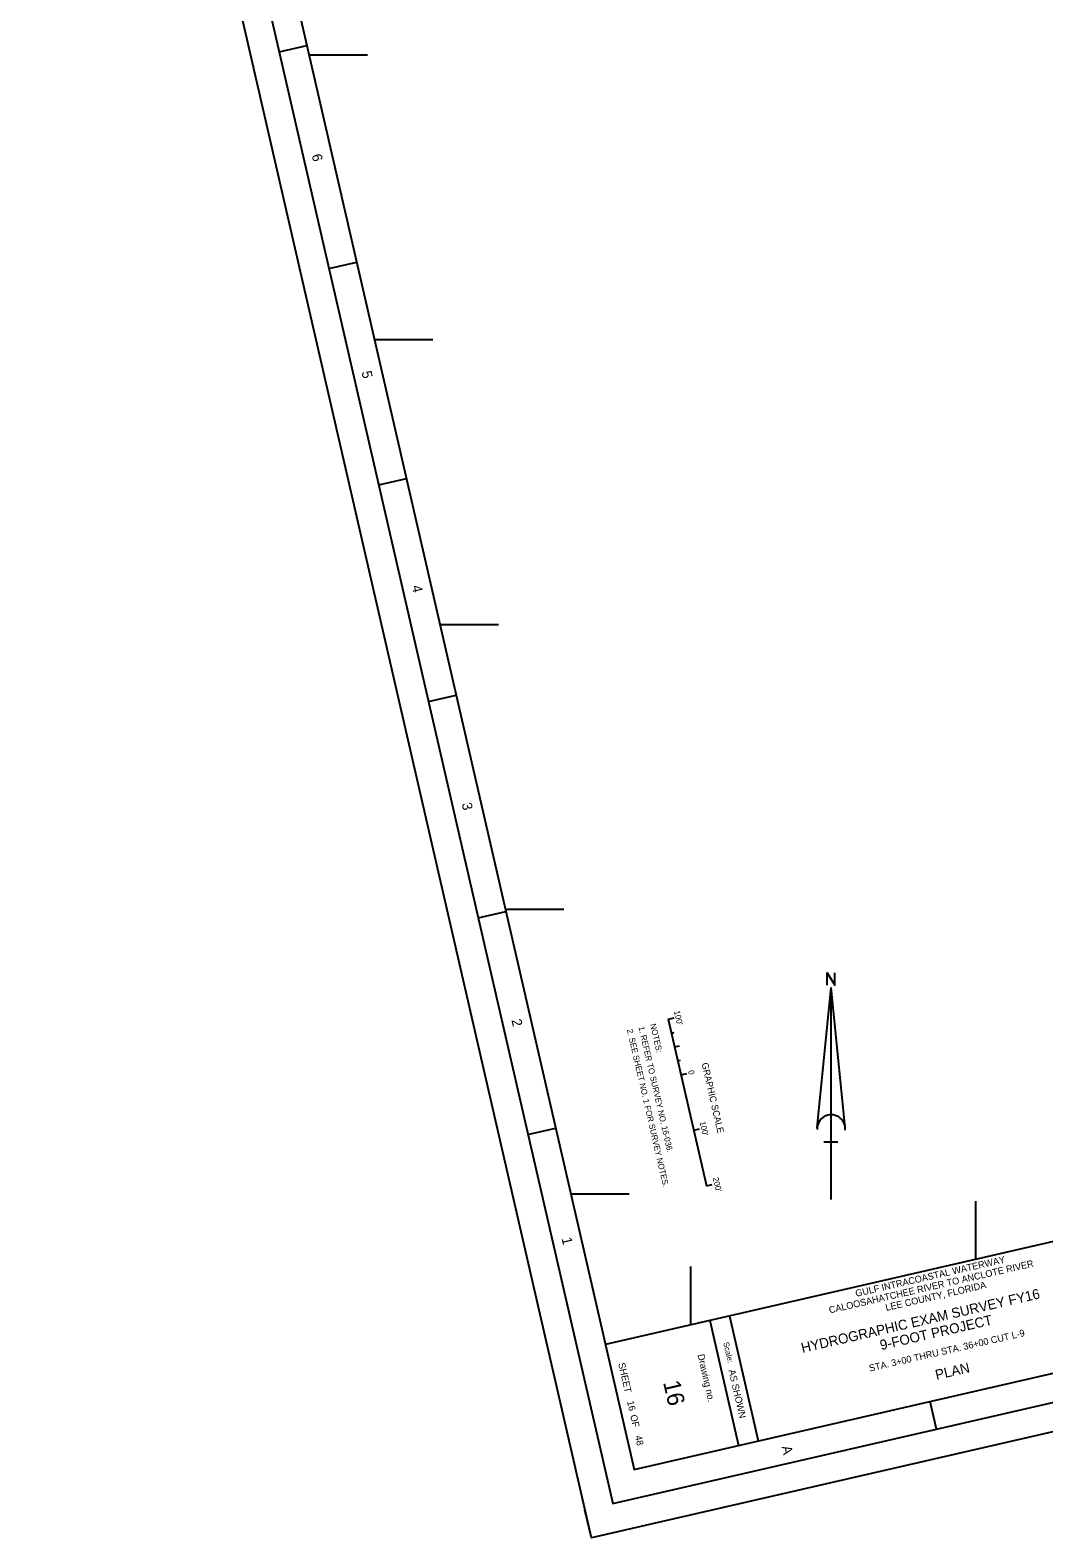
# Model space of a CAD drawing. Extents: x 604840 to 609139, y 785896 to 790946.
# Drawn here: x 604840 to 606620, y 785896 to 788543 of the extents above; entities that cross this region are included whole.
import ezdxf

# ---------------------------------------------------------------- set-up
doc = ezdxf.new("R2010")
doc.units = 0
for name, color, linetype in [('G-ANNO-NPLT', 7, 'Continuous'), ('G-ANNO-TEXT-DRWG', 7, 'Continuous'), ('G-ANNO-TEXT-PROJ', 7, 'Continuous'), ('G-ANNO-TEXT-TTLB', 7, 'Continuous'), ('G-ANNO-TTLB', 7, 'Continuous'), ('V-ANNO-NOTE', 7, 'Continuous'), ('V-ANNO-SYMB', 7, 'Continuous'), ('V-TOPO-COOR-STAT', 7, 'Continuous')]:
    doc.layers.add(name, color=color, linetype=linetype)

msp = doc.modelspace()

# ---------------------------------------------------------------- linework, layer by layer
at = {"layer": 'G-ANNO-NPLT'}
msp.add_lwpolyline([(608153.4, 790946.1), (609138.7, 786657.8), (605825.1, 785896.5), (604839.8, 790184.7)], close=True, dxfattribs=at)
msp.add_lwpolyline([(605873.8, 785907.5), (605825.1, 785896.3), (605813.9, 785945.1)], dxfattribs=at)
at = {"layer": 'G-ANNO-TTLB'}
for p, q in [((605277, 788505), (605325.7, 788516.1)), ((605364.3, 788124.9), (605413.1, 788136.1)), ((605451.7, 787744.8), (605500.4, 787756)), ((605539, 787364.7), (605587.7, 787375.9)), ((605626.3, 786984.6), (605675.1, 786995.8)), ((608968.4, 786952.2), (605849.7, 786235.6)), ((605713.7, 786604.5), (605762.4, 786615.7)), ((606033, 786277.7), (606083.4, 786058.4)), ((606067.8, 786285.7), (606118.2, 786066.4)), ((606431.1, 786087), (606419.9, 786135.7))]:
    msp.add_line(p, q, dxfattribs=at)
for points in [[(604899.7, 790147.2), (605862.6, 785956.4), (609078.8, 786695.3), (608115.9, 790886.1)], [(609018.8, 786732.9), (608095.1, 790753.1), (604976.4, 790036.5), (605900.1, 786016.3)]]:
    msp.add_lwpolyline(points, close=True, dxfattribs=at)
at = {"layer": 'V-ANNO-NOTE'}
for p, q in [((605960.1, 786806.8), (605970.3, 786809.2)), ((605960.1, 786806.8), (606027.2, 786514.4)), ((605965.7, 786782.5), (605970.3, 786783.5)), ((605971.3, 786758.1), (605979.6, 786760)), ((605976.9, 786733.7), (605981.5, 786734.8)), ((605982.5, 786709.4), (605992.6, 786711.7)), ((605982.5, 786709.4), (605992.6, 786711.7)), ((605982.5, 786709.4), (605987.3, 786710.5)), ((606004.9, 786611.9), (606015, 786614.2)), ((606027.2, 786514.4), (606037.4, 786516.8))]:
    msp.add_line(p, q, dxfattribs=at)
at = {"layer": 'V-ANNO-SYMB'}
for p, q in [((606221.4, 786616.8), (606246.1, 786862.5)), ((606246.1, 786490.2), (606246.1, 786862.5)), ((606270.8, 786616.8), (606246.1, 786862.5)), ((606257.8, 786590.7), (606233, 786590.7))]:
    msp.add_line(p, q, dxfattribs=at)
msp.add_lwpolyline([(606239.2, 786866.5), (606239.2, 786888.2), (606252.7, 786866.5), (606252.7, 786888.2)], dxfattribs=at)
msp.add_arc((606246.1, 786614.3), 24.8, 355.2984, 182.0673, dxfattribs=at)
at = {"layer": 'V-TOPO-COOR-STAT'}
for p, q in [((605329.4, 788500), (605432.1, 788500)), ((605444.3, 788000), (605546.9, 788000)), ((605559.2, 787500), (605661.8, 787500)), ((605674.1, 787000), (605776.7, 787000)), ((605789, 786500), (605891.6, 786500)), ((606500, 786385), (606500, 786487.6)), ((606000, 786270.1), (606000, 786372.7))]:
    msp.add_line(p, q, dxfattribs=at)

# ---------------------------------------------------------------- texts
at = {"layer": 'G-ANNO-TEXT-DRWG'}
for s, height, rotation, p in [('STA. 3+00 THRU STA. 36+00 CUT L-9', 12, 12.9401, (606314, 786188)), ('PLAN', 17.5, 12.9401, (606431.1, 786173.6)), ('16', 30, 282.9401, (605950.9, 786169.3)), (' 16          48', 12, 282.9401, (605886.6, 786139.9))]:
    msp.add_text(s, height=height, rotation=rotation, dxfattribs=at).set_placement(p)
at = {"layer": 'G-ANNO-TEXT-PROJ'}
for s, height, p in [('CALOOSAHATCHEE RIVER TO ANCLOTE RIVER', 12, (606243.6, 786290.2)), ('GULF INTRACOASTAL WATERWAY', 12, (606290, 786319.3)), ('LEE COUNTY, FLORIDA', 12, (606342.9, 786294.5)), ('HYDROGRAPHIC EXAM SURVEY FY16', 17.5, (606195.7, 786220.9)), ('9-FOOT PROJECT', 17.5, (606333.9, 786225.8))]:
    msp.add_text(s, height=height, rotation=12.9401, dxfattribs=at).set_placement(p)
at = {"layer": 'G-ANNO-TEXT-TTLB'}
for s, height, p in [('Scale:', 10, (606056.6, 786238.9)), ('Drawing no.', 12, (606011.3, 786217.5)), ('SHEET         OF', 12, (605872.2, 786202.3)), ('AS SHOWN', 12, (606065.8, 786190.4))]:
    msp.add_text(s, height=height, rotation=282.9401, dxfattribs=at).set_placement(p)
at = {"layer": 'G-ANNO-TTLB'}
for s, p in [('6', (605334, 788323.8)), ('5', (605421.5, 787942.9)), ('4', (605509.6, 787566.9)), ('3', (605597.4, 787185)), ('2', (605684.7, 786805.2)), ('1', (605772.7, 786422)), ('A', (606158.9, 786056.2))]:
    msp.add_text(s, height=17.5, rotation=282.9401, dxfattribs=at).set_placement(p)
at = {"layer": 'V-ANNO-NOTE'}
for s, height, p in [("100'", 10.42, (605970, 786820.7)), ('NOTES:', 10.42, (605928.1, 786797.7)), ('2. SEE SHEET NO. 1 FOR SURVEY NOTES.', 10.416, (605887.5, 786788.4)), ('1. REFER TO SURVEY NO. 16-036.', 10.416, (605907.8, 786793)), ('0', 10.4, (605994.7, 786716)), ('GRAPHIC SCALE', 11.666, (606018.5, 786729.1)), ("100'", 10.42, (606015, 786626.2)), ("200'", 10.42, (606038.1, 786528.3))]:
    msp.add_text(s, height=height, rotation=282.9401, dxfattribs=at).set_placement(p)

doc.saveas('drawing.dxf')
